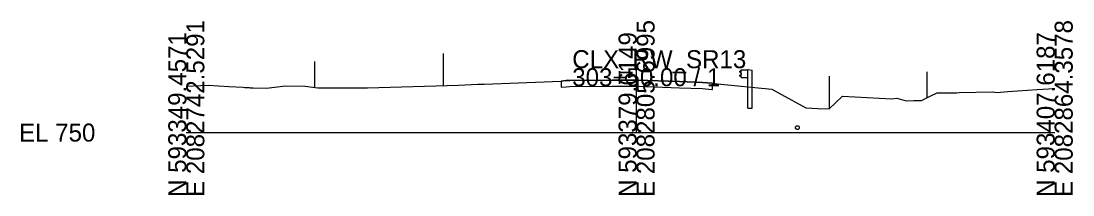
# Model space of a CAD drawing. Extents: x -26 to 2138, y -10 to 4518.
# Drawn here: x 974.3 to 1137.8, y 2990.3 to 3017.3 of the extents above; entities that cross this region are included whole.
import ezdxf

# ---------------------------------------------------------------- set-up
doc = ezdxf.new("R2010")
doc.units = 0
for name, color, linetype in [('GK_Cells', 7, 'Continuous'), ('MD_X_Asphalt_Pavement', 7, 'Continuous'), ('RD_P_Cells', 7, 'Continuous'), ('RW_P_Esmt_SH', 7, 'Continuous'), ('RW_X_Esmt_SH', 7, 'Continuous'), ('UT_X_Water', 7, 'Continuous'), ('XS_X_Ground_Line', 7, 'Continuous')]:
    doc.layers.add(name, color=color, linetype=linetype)

msp = doc.modelspace()

# ---------------------------------------------------------------- linework, layer by layer
at = {"layer": 'GK_Cells'}
for p, q in [((1070, 3000), (1070, 3010)), ((1000, 3000), (1070, 3000)), ((1070, 3000), (1135, 3000))]:
    msp.add_line(p, q, dxfattribs=at)
at = {"layer": 'MD_X_Asphalt_Pavement'}
msp.add_lwpolyline([(1059.07, 3008.07), (1058.3, 3008.01), (1058.3, 3007.05), (1059.07, 3007.12), (1059.64, 3007.14), (1066.21, 3007.19), (1070.08, 3007.2), (1076.69, 3006.97), (1080.26, 3006.83), (1081.7, 3006.71), (1081.78, 3006.71), (1081.78, 3007.66), (1081.7, 3007.67), (1080.26, 3007.79), (1076.69, 3007.93), (1070.08, 3008.16), (1066.21, 3008.15), (1059.64, 3008.1), (1059.07, 3008.07)], dxfattribs=at)
at = {"layer": 'RD_P_Cells'}
for p, q in [((1086.03, 3009.53), (1086.19, 3009.65)), ((1086.24, 3009.26), (1086.03, 3009.4)), ((1086.03, 3008.9), (1086.24, 3009.04)), ((1086.19, 3009.65), (1086.28, 3009.66)), ((1086.27, 3009.15), (1086.27, 3009.2)), ((1086.27, 3009.1), (1086.27, 3009.15)), ((1086.28, 3008.56), (1086.28, 3009.74)), ((1086.28, 3009.74), (1087.28, 3009.74)), ((1087.28, 3009.74), (1087.36, 3009.79)), ((1087.28, 3003.79), (1087.28, 3009.74)), ((1087.36, 3009.79), (1087.9, 3009.7)), ((1087.9, 3009.7), (1087.95, 3009.68)), ((1087.95, 3003.79), (1087.95, 3009.68)), ((1086.19, 3008.66), (1086.03, 3008.77)), ((1086.28, 3008.64), (1086.19, 3008.66)), ((1086.28, 3008.56), (1087.28, 3008.56)), ((1087.28, 3003.79), (1087.95, 3003.79))]:
    msp.add_line(p, q, dxfattribs=at)
for points in [[(1086.26, 3009.18), (1086.26, 3009.12), (1086.24, 3009.12), (1086.24, 3009.18)], [(1086.26, 3009.21), (1086.26, 3009.09), (1086.27, 3009.09), (1086.27, 3009.21)]]:
    msp.add_lwpolyline(points, close=True, dxfattribs=at)
for centre, start, end in [((1086.08, 3009.47), 125.2323, 235.038), ((1086.19, 3009.2), 0, 55.038), ((1086.19, 3009.1), 304.962, 0), ((1086.08, 3008.83), 125.2323, 235.038)]:
    msp.add_arc(centre, 0.0781, start, end, dxfattribs=at)
at = {"layer": 'RW_P_Esmt_SH'}
for p, q in [((1020, 3007.02), (1020, 3011.02)), ((1115.17, 3005.42), (1115.17, 3009.42))]:
    msp.add_line(p, q, dxfattribs=at)
at = {"layer": 'RW_X_Esmt_SH'}
for p, q in [((1040, 3007.3), (1040, 3012.3)), ((1100, 3003.74), (1100, 3008.74))]:
    msp.add_line(p, q, dxfattribs=at)
at = {"layer": 'UT_X_Water'}
msp.add_circle((1095, 3000.77), 0.3, dxfattribs=at)
at = {"layer": 'XS_X_Ground_Line'}
msp.add_lwpolyline([(1000, 3007.22), (1003.42, 3007.38), (1006.59, 3007.15), (1008.84, 3007.04), (1009.11, 3007.02), (1009.24, 3007.01), (1009.65, 3006.99), (1009.67, 3006.99), (1009.68, 3006.98), (1009.79, 3006.98), (1009.94, 3006.97), (1010, 3006.96), (1010.02, 3006.96), (1010.07, 3006.96), (1010.17, 3006.95), (1010.2, 3006.95), (1010.31, 3006.94), (1010.32, 3006.94), (1010.32, 3006.94), (1010.35, 3006.94), (1010.36, 3006.94), (1010.37, 3006.94), (1012.46, 3006.88), (1015.42, 3007.25), (1018.47, 3007.23), (1020.47, 3006.95), (1020.6, 3006.95), (1028.15, 3006.97), (1042.33, 3007.37), (1045.33, 3007.53), (1045.71, 3007.51), (1046.1, 3007.52), (1046.3, 3007.54), (1058.3, 3008.01), (1059.07, 3008.07), (1059.64, 3008.1), (1066.21, 3008.15), (1070.08, 3008.16), (1076.69, 3007.93), (1080.26, 3007.79), (1081.7, 3007.67), (1081.78, 3007.66), (1082.57, 3007.59), (1091.04, 3006.74), (1092.53, 3005.92), (1096.31, 3003.85), (1098.16, 3003.73), (1099.94, 3003.69), (1100.94, 3004.6), (1101.99, 3005.66), (1109.67, 3005.23), (1110.44, 3005.34), (1111.91, 3004.92), (1113.12, 3004.97), (1114.29, 3005), (1115.74, 3005.7), (1116.74, 3006.17), (1118.83, 3006.17), (1119.18, 3006.18), (1119.76, 3006.19), (1120.13, 3006.2), (1125.36, 3006.32), (1125.98, 3006.23), (1127.74, 3006.37), (1129.98, 3006.55), (1130.77, 3006.6), (1132.27, 3006.7), (1134.02, 3006.82), (1135, 3006.87)], dxfattribs=at)

# ---------------------------------------------------------------- texts
msp.add_text('-', height=0.0001).set_placement((1000, 3000))
at = {"layer": 'GK_Cells'}
for s, p in [('E 2082742.5291', (1002.8, 2990)), ('E 2082805.6995', (1072.8, 2990)), ('E 2082864.3578', (1137.8, 2990)), ('N 593349.4571', (1000, 2990)), ('N 593379.6149', (1070, 2990)), ('N 593407.6187', (1135, 2990))]:
    msp.add_text(s, height=2.8, rotation=90, dxfattribs=at).set_placement(p)
for s, p in [('CLX_RW_SR13', (1060, 3010)), ('303+50.00 / 1', (1060, 3007.2)), ('EL 750', (974, 2998.6))]:
    msp.add_text(s, height=2.8, dxfattribs=at).set_placement(p)

doc.saveas('drawing.dxf')
